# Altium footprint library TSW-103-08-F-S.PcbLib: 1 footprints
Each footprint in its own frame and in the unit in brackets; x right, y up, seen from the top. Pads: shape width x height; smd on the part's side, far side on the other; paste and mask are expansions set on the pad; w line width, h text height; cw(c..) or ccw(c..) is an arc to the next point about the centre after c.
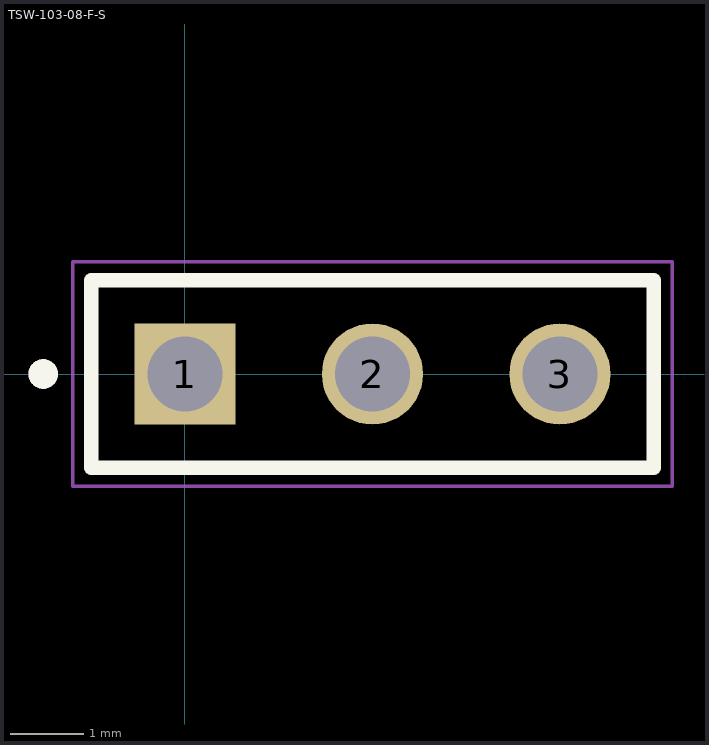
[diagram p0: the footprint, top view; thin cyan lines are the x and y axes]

## TSW-103-08-F-S [mm]
pads (3):
  rect 1.37x1.37 hole 1.02: 1(0,0)
  round 1.37 hole 1.02: 2(2.54,0) 3(5.08,0)
Top Overlay:
  circle w0.2: c-1.92,0 r0.1
  lines w0.2: -1.27,-1.27 -1.27,1.27 6.35,1.27 6.35,-1.27 -1.27,-1.27
Mechanical 13:
  circle w0.2: c-1.92,0 r0.1
  lines w0.1: -1.27,-1.27 -1.27,1.27 6.35,1.27 6.35,-1.27 -1.27,-1.27
Mechanical 15:
  lines w0.05: -1.52,-1.52 -1.52,1.52 6.6,1.52 6.6,-1.52 -1.52,-1.52
3D body "TSW-103-08-F-S.stp": height 8.38, standoff -5.08, extent -1.397,-1.27 6.35,1.27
